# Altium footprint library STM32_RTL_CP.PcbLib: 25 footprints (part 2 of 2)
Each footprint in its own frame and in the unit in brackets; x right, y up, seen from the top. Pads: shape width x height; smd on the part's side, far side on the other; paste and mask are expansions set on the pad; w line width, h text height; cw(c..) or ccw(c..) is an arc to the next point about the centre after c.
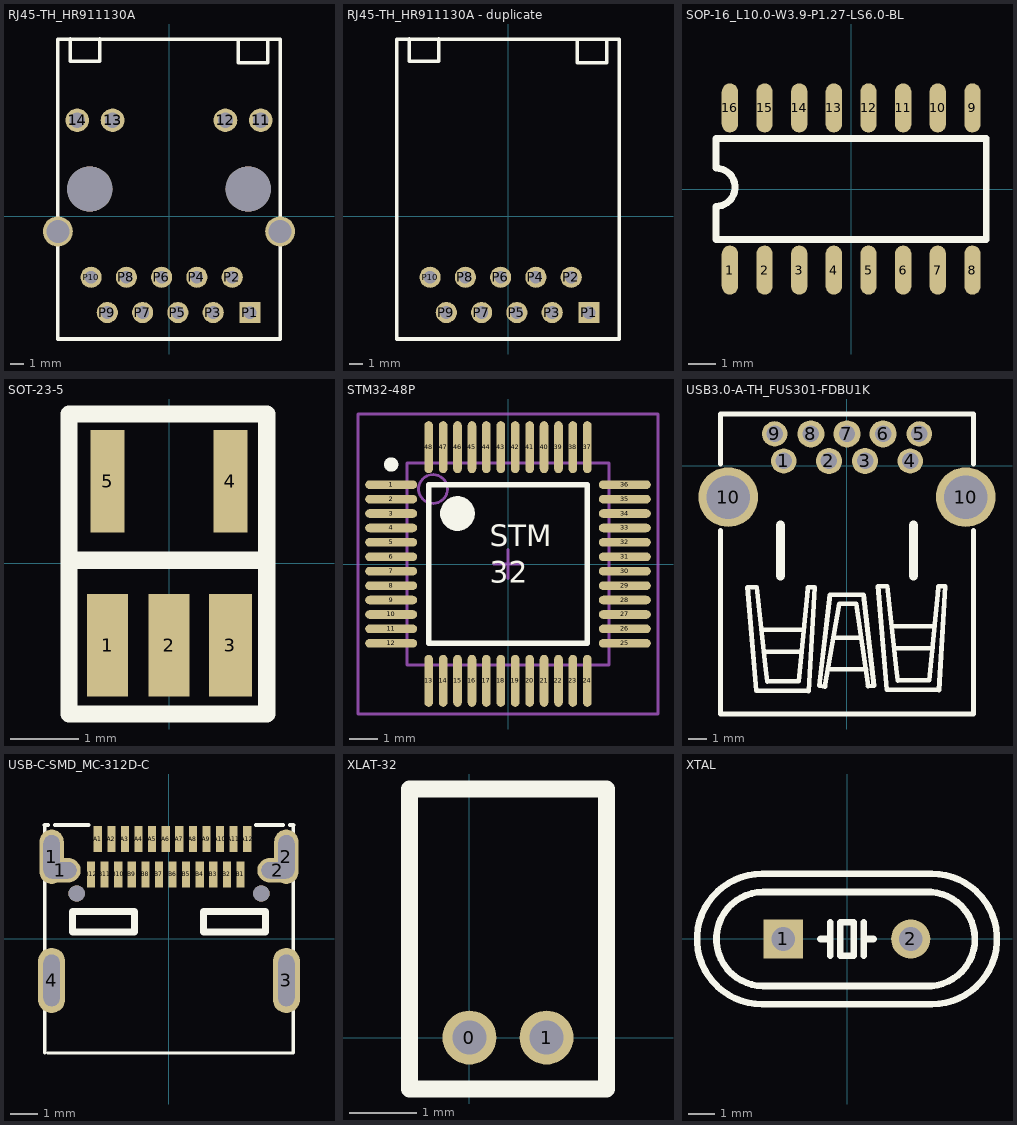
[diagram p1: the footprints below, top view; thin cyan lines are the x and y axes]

## RJ45-TH_HR911130A [mil]
pads (18):
  round 66.93 hole 43.31: 11(260,272.62) 12(160,272.62) 13(-160,272.62) 14(-260,272.62)
  rect 60x60 hole 35.83: P1(229.63,-272.62)
  round 60 hole 35.83: P2(179.1,-172.38) P3(125.2,-272.38) P4(79.1,-172.38) P5(25.2,-272.38) P6(-20.9,-172.38) P7(-74.8,-272.38) P8(-120.9,-172.38) P9(-174.8,-272.38) P10(-220.9,-172.38)
  round 85 hole 65: SHIELD0(-315,-42.48) SHIELD1(315,-42.48)
  round 127.95 hole 127.95 unplated: ""(-224.4,77.62) ""(224.4,77.62)
Top Overlay:
  lines w10: -279.53,502.82 -279.53,439.82 -196.85,439.82 -196.85,471.32 -196.85,502.82 ; 196.82,498.88 196.82,435.88 279.5,435.88 279.5,467.38 279.5,498.88 ; -315,-347.38 -315,502.62 315,502.62 315,-347.38 -315,-347.38

## RJ45-TH_HR911130A - duplicate [mil]
pads (10):
  rect 60x60 hole 35.83: P1(229.63,-272.62)
  round 60 hole 35.83: P2(179.1,-172.38) P3(125.2,-272.38) P4(79.1,-172.38) P5(25.2,-272.38) P6(-20.9,-172.38) P7(-74.8,-272.38) P8(-120.9,-172.38) P9(-174.8,-272.38) P10(-220.9,-172.38)
Top Overlay:
  lines w10: -279.53,502.82 -279.53,439.82 -196.85,439.82 -196.85,471.32 -196.85,502.82 ; 196.82,498.88 196.82,435.88 279.5,435.88 279.5,467.38 279.5,498.88 ; -315,-347.38 -315,502.62 315,502.62 315,-347.38 -315,-347.38

## SOP-16_L10.0-W3.9-P1.27-LS6.0-BL [mm]
pads (16):
  oval 0.6x1.8 smd: 1(-4.445,-2.972) 2(-3.175,-2.972) 3(-1.905,-2.972) 4(-0.635,-2.972) 5(0.635,-2.972) 6(1.905,-2.972) 7(3.175,-2.972) 8(4.445,-2.972) 9(4.445,2.972) 10(3.175,2.972) 11(1.905,2.972) 12(0.635,2.972) 13(-0.635,2.972) 14(-1.905,2.972) 15(-3.175,2.972) 16(-4.445,2.972)
Top Overlay:
  lines w0.254: -4.953,0.762 cw(c-4.953,0.064) -4.953,-0.635 -4.953,-1.85 -4.95,-1.85 4.95,-1.85 4.95,1.85 -4.95,1.85 -4.95,0.762

## SOT-23-5 [mm]
height 4.32
pads (5):
  rect 0.6x1.5 smd: 1(-0.9,-1.2) 2(0,-1.2)
  rect 0.63x1.5 smd: 3(0.9,-1.2)
  rect 0.5x1.5 smd: 4(0.9,1.2) 5(-0.9,1.2)
Top Overlay:
  lines w0.254: -1.466,0.041 1.43,0.041 ; -1.466,-2.21 -1.466,2.184 1.43,2.184 1.43,-2.21 -1.466,-2.21

## STM32-48P [mm]
height 4.32
pads (48):
  oval 1.8x0.3 smd: 1(-4.05,2.75) 2(-4.05,2.25) 3(-4.05,1.75) 4(-4.05,1.25) 5(-4.05,0.75) 6(-4.05,0.25) 7(-4.05,-0.25) 8(-4.05,-0.75) 9(-4.05,-1.25) 10(-4.05,-1.75) 11(-4.05,-2.25) 12(-4.05,-2.75) 25(4.05,-2.75) 26(4.05,-2.25) 27(4.05,-1.75) 28(4.05,-1.25) 29(4.05,-0.75) 30(4.05,-0.25) 31(4.05,0.25) 32(4.05,0.75) 33(4.05,1.25) 34(4.05,1.75) 35(4.05,2.25) 36(4.05,2.75)
  oval 0.3x1.8 smd: 13(-2.75,-4.05) 14(-2.25,-4.05) 15(-1.75,-4.05) 16(-1.25,-4.05) 17(-0.75,-4.05) 18(-0.25,-4.05) 19(0.25,-4.05) 20(0.75,-4.05) 21(1.25,-4.05) 22(1.75,-4.05) 23(2.25,-4.05) 24(2.75,-4.05) 37(2.75,4.05) 38(2.25,4.05) 39(1.75,4.05) 40(1.25,4.05) 41(0.75,4.05) 42(0.25,4.05) 43(-0.25,4.05) 44(-0.75,4.05) 45(-1.25,4.05) 46(-1.75,4.05) 47(-2.25,4.05) 48(-2.75,4.05)
Top Overlay:
  circle w0.6: c-1.75,1.75 r0.3
  circle w0.25: c-4.05,3.45 r0.125
  lines w0.2: -2.75,-2.75 2.75,-2.75 2.75,2.75 -2.75,2.75 -2.75,-2.75
  text "STM / 32" at -0.635,-0.889 h1.27
Mechanical 13:
  circle w0.1: c-2.6,2.6 r0.5
  lines w0.1: -3.5,-3.5 3.5,-3.5 3.5,3.5 -3.5,3.5 -3.5,-3.5
Mechanical 15:
  lines w0.1: -0.5,0 0.5,0 ; 0,-0.5 0,0.5 ; -5.2,-5.2 5.2,-5.2 5.2,5.2 -5.2,5.2 -5.2,-5.2
3D body: height 1.6, standoff 0, extent -3.5,-3.5 3.5,3.5

## USB3.0-A-TH_FUS301-FDBU1K [mm]
pads (11):
  round 1.4 hole 0.914: 1(-3.5,0.25) 4(3.5,0.25)
  round 1.45 hole 0.914: 2(-1,0.25) 3(1,0.25)
  round 1.4 hole 0.9: 5(4,1.75) 9(-4,1.75)
  round 1.5 hole 0.9: 6(2,1.75) 7(0,1.75) 8(-2,1.75)
  round 3.3 hole 2.4: 10(-6.57,-1.75) 10(6.57,-1.75)
Top Overlay:
  lines w0.254: -7,-3.581 -7,-13.75 7,-13.75 7,-3.581 ; -7,0.081 -7,2.85 -4.791,2.85 4.791,2.85 7,2.85 7,0.081 ; -4.668,-9.098 -2.408,-9.098 ; -4.529,-10.308 -2.499,-10.308 ; -1.016,-11.282 1.067,-11.282 ; -0.711,-9.529 0.737,-9.529 ; 2.562,-8.901 4.822,-8.901 ; 2.702,-10.111 4.732,-10.111 ; -5.506,-6.732 -5.011,-12.467 -2.128,-12.478 -1.778,-6.735 -2.158,-6.735 -2.188,-7.165 -2.662,-11.943 -4.412,-11.954 -4.487,-11.276 -4.997,-6.735 -5.506,-6.732 ; -1.524,-12.196 -0.94,-7.141 0.914,-7.141 1.495,-12.188 1.164,-12.214 0.508,-7.649 -0.432,-7.649 -1.219,-12.247 -1.524,-12.196 ; 1.714,-6.674 2.209,-12.409 5.092,-12.421 5.442,-6.678 5.062,-6.678 5.032,-7.108 4.558,-11.886 2.808,-11.897 2.733,-11.218 2.223,-6.678 1.714,-6.674
  lines w0.5: -3.683,-6.1 -3.683,-3.306 ; 3.683,-6.1 3.683,-3.306

## USB-C-SMD_MC-312D-C [mm]
pads (32):
  oval 0.9x2 hole 0.6 slot 1.6 at 90 deg: 1(-4.32,3.018) 2(4.32,3.018)
  oval 1.5x0.9 hole 0.6 slot 1.2 at 0 deg: 1(-4,2.518) 2(4,2.518)
  oval 1x2.4 hole 0.6 slot 1.9 at 90 deg: 3(4.32,-1.532) 4(-4.32,-1.532)
  rect 0.3x0.95 smd: A1(-2.62,3.668) A2(-2.12,3.668) A3(-1.62,3.668) A4(-1.12,3.668) A5(-0.62,3.668) A6(-0.12,3.668) A7(0.38,3.668) A8(0.88,3.668) A9(1.38,3.668) A10(1.88,3.668) A11(2.38,3.668) A12(2.88,3.668) B1(2.63,2.368) B2(2.13,2.368) B3(1.63,2.368) B4(1.13,2.368) B5(0.63,2.368) B6(0.13,2.368) B7(-0.37,2.368) B8(-0.87,2.368) B9(-1.37,2.368) B10(-1.87,2.368) B11(-2.37,2.368) B12(-2.87,2.368)
  round 0.6 hole 0.6 unplated: ""(-3.4,1.668) ""(3.4,1.668)
Top Overlay:
  lines w0.12: -4.572,-4.199 -4.572,4.183 ; -4.47,-4.199 4.47,-4.199 ; 4.445,-4.199 4.572,-4.199 4.572,4.183
  lines w0.152: -4.572,4.183 -4.447,4.183 ; -4.192,4.183 -2.956,4.183 ; 3.196,4.183 4.193,4.183 ; 4.447,4.183 4.572,4.183
  lines w0.254: -3.556,0.246 -1.27,0.246 -1.27,1.008 -3.556,1.008 -3.556,0.246 ; 1.27,0.246 3.556,0.246 3.556,1.008 1.27,1.008 1.27,0.246
Top Paste:
  drawing of 28 lines, arcs and shapes, not listed
Mechanical 15:
  circle w0.225: c3.4,1.668 r0.113
  circle w0.225: c-3.4,1.668 r0.113

## XLAT-32 [mm]
pads (2):
  round 0.8 hole 0.5: 0(0,0) 1(1.143,0)
Top Overlay:
  lines w0.254: -0.889,-0.762 2.032,-0.762 2.032,3.683 -0.889,3.683 -0.889,-0.762
Bottom Overlay:
  region: 0,0

## XTAL [mm]
pads (2):
  rect 1.5x1.5 hole 0.9: 1(-2.44,0)
  round 1.5 hole 0.9: 2(2.44,0)
Top Overlay:
  lines w0.254: -3.251,2.499 ccw(c-3.243,0) -3.25,-2.5 ; -3.25,-2.5 3.25,-2.5 ; -3.25,2.5 3.25,2.5 cw(c3.243,0) 3.251,-2.499 ; -3.2,1.8 3.2,1.8 cw(c3.093,0) 3,-1.801 ; -3.2,1.801 ccw(c-3.2,0) -3.2,-1.8 3,-1.8 ; -1.016,0 -0.635,0 ; -0.635,-0.635 -0.635,0 ; -0.635,0.635 -0.635,0 ; 0.635,-0.635 0.635,0 ; 0.635,0.635 0.635,0 ; 1.016,0 0.635,0 ; -0.254,-0.635 0.254,-0.635 0.254,0.635 -0.254,0.635 -0.254,-0.635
